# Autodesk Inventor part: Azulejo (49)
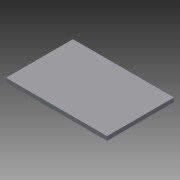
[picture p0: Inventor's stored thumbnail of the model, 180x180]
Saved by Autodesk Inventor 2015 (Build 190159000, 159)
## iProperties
Created: 2015-04
Part Number: Azulejo (49)
Material: Genérico
Document SubType Name: Modeling
Designer: Felipe
Density: 1 g/cm^3
Appearance: Padrão
Author: Felipe
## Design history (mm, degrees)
sketch "Sketch1"
  geometry: L1 (-5999.978, 1162.687)-(-5915.126, 1162.687); L2 (6980.022, 1162.687)-(6895.169, 1162.687); L3 (-1034.12, -6357.313)-(-1063.775, -6417.313); L4 (-5519.978, 1582.687)-(-6306.841, 1582.687); L5 (5000.022, -4857.313)-(6000.022, -4857.313); L6 (6000.022, -4857.313)-(6000.022, -6277.313); L7 (6000.022, -4837.313)-(5000.022, -4837.313); L8 (5000.022, -4837.313)-(5000.022, -3357.313); L9 (5000.022, -3357.313)-(6000.022, -3357.313); L10 (6000.022, -3357.313)-(6000.022, -4837.313); L11 (6000.022, -3337.313)-(5000.022, -3337.313); L12 (5000.022, -3337.313)-(5000.022, -1857.313); L13 (5000.022, -1857.313)-(6000.022, -1857.313); L14 (6000.022, -1857.313)-(6000.022, -3337.313); L15 (6000.022, -1837.313)-(5000.022, -1837.313); L16 (5000.022, -1837.313)-(5000.022, -357.313); L17 (5000.022, -357.313)-(6000.022, -357.313); L18 (6000.022, -357.313)-(6000.022, -1837.313); L19 (4000.022, -4837.313)-(3500.022, -4837.313); L20 (3500.022, -4837.313)-(3500.022, -3357.313); L21 (3500.022, -3357.313)-(4000.022, -3357.313); L22 (4000.022, -3357.313)-(4000.022, -4837.313); L23 (4000.022, -3337.313)-(3500.022, -3337.313); L24 (3500.022, -3337.313)-(3500.022, -1857.313); L25 (2000.022, 2662.687)-(2480.022, 2662.687); L26 (500.022, 2662.687)-(1980.022, 2662.687); L27 (-999.978, 2662.687)-(480.022, 2662.687); L28 (3500.022, -1857.313)-(4000.022, -1857.313); L29 (4000.022, -1857.313)-(4000.022, -3337.313); L30 (4000.022, -1837.313)-(3500.022, -1837.313); L31 (3500.022, -1837.313)-(3500.022, -357.313); L32 (3500.022, -357.313)-(4000.022, -357.313); L33 (4000.022, -357.313)-(4000.022, -1837.313); L34 (-5519.978, 1142.687)-(-5519.978, -337.313); L35 (6500.022, -337.313)-(6500.022, 1142.687); L36 (6480.022, 2662.687)-(5000.022, 2662.687); L37 (5000.022, 2642.687)-(6480.022, 2642.687); L38 (6480.022, 1142.687)-(6480.022, -337.313); L39 (6480.022, -337.313)-(5000.022, -337.313); L40 (5000.022, -337.313)-(5000.022, 1142.687); L41 (7965.922, 2662.687)-(6500.022, 2662.687); L42 (6500.022, 2642.687)-(7965.922, 2642.687); L43 (4980.022, 2662.687)-(3500.022, 2662.687); L44 (3500.022, 2642.687)-(4980.022, 2642.687); L45 (4980.022, 1142.687)-(4980.022, -337.313); L46 (4980.022, -337.313)-(3500.022, -337.313); L47 (3500.022, -337.313)-(3500.022, 1142.687); L48 (3500.022, -1837.313)-(3500.022, -357.313); L49 (3500.022, -3337.313)-(3500.022, -1857.313); L50 (3500.022, -4837.313)-(3500.022, -3357.313); L51 (3500.022, -6257.313)-(3500.022, -4857.313); L52 (4000.022, -6277.313)-(3500.022, -6277.313); L53 (3500.022, -6277.313)-(3500.022, -4857.313); L54 (3480.022, 1162.687)-(2000.022, 1162.687); L55 (2000.022, 1142.687)-(3480.022, 1142.687); L56 (3480.022, 1142.687)-(3480.022, -337.313); L57 (3480.022, -337.313)-(2000.022, -337.313); L58 (2000.022, -337.313)-(2000.022, 1142.687); L59 (3480.022, -357.313)-(3480.022, -1837.313); L60 (3480.022, -1857.313)-(3480.022, -3337.313); L61 (3480.022, -3357.313)-(3480.022, -4837.313); L62 (3480.022, -4857.313)-(3480.022, -6277.313); L63 (3500.022, -4857.313)-(4000.022, -4857.313); L64 (1980.022, 1162.687)-(500.022, 1162.687)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; 3 further points
  constraints: 1802 end point, 96 point on line, 2 other
extrude "Extrusion1" new body sketch "Sketch1" distance "d0" = 60; taper "d1" = 0 deg
body "Solid1"
